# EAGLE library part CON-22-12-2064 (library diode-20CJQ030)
CONNECTOR wire to board 2.54 mm (.1 inch) pitch header
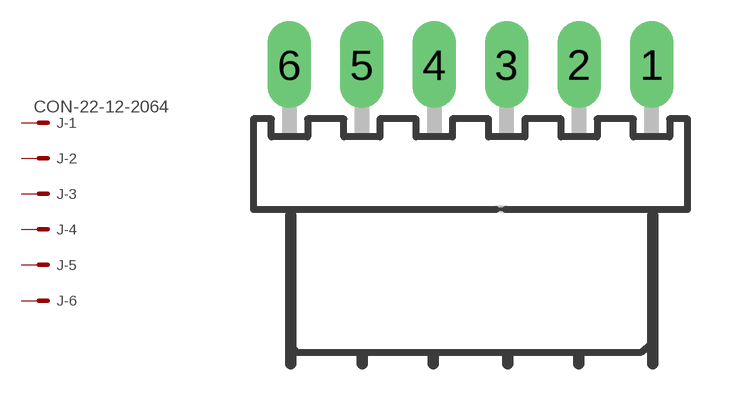
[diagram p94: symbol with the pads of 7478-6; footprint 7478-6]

Designator prefix J; gates -1=MV -2=M -3=M -4=M -5=M -6=M

## CON-22-12-2064-  [7478-6]
1  -1:S  pas
2  -2:S  pas
3  -3:S  pas
4  -4:S  pas
5  -5:S  pas
6  -6:S  pas

## Footprint 7478-6 (pad centres in mm)
MOLEX 2.54mm KK RA CONNECTOR Fixed Orientation
drill 1.02 long: 1 6.35,0; 2 3.81,0; 3 1.27,0; 4 -1.27,0; 5 -3.81,0; 6 -6.35,0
